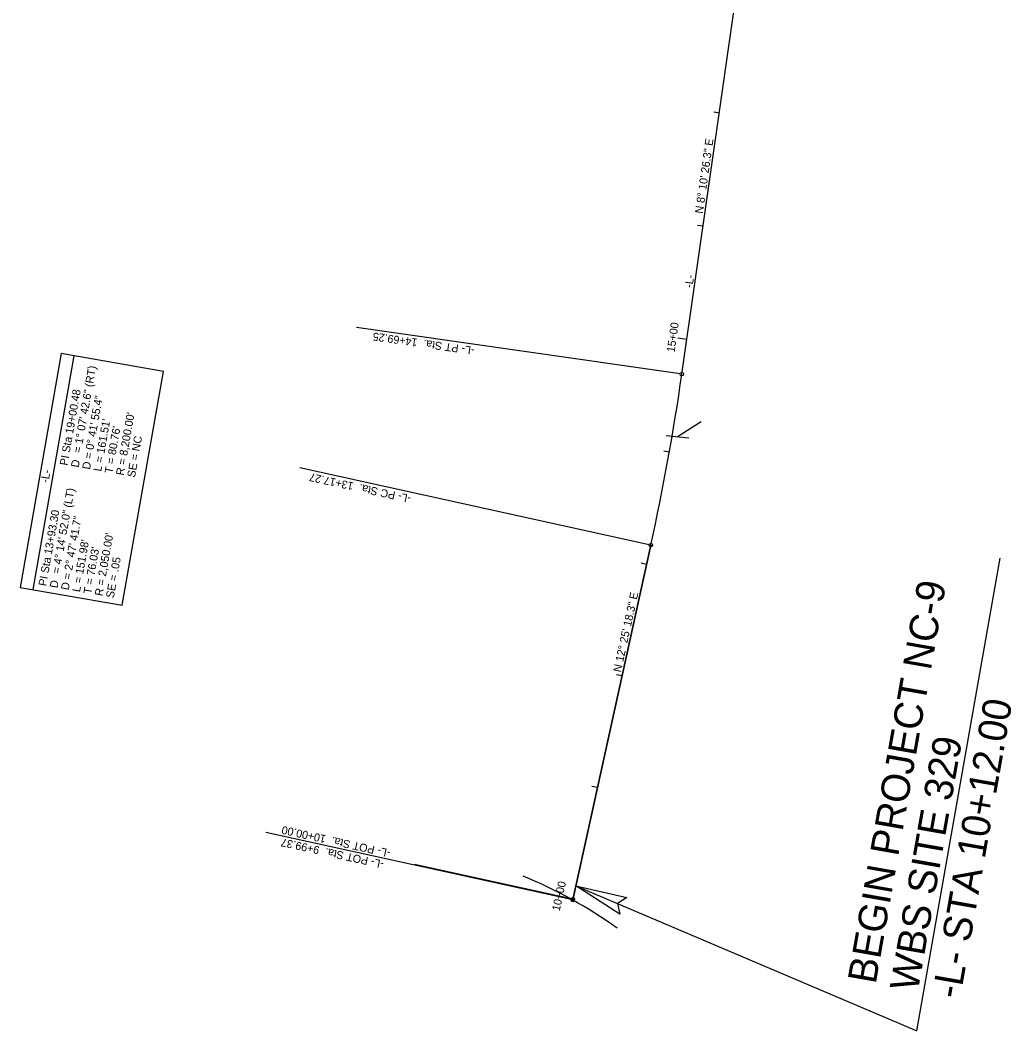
# Model space of a CAD drawing. Extents: x 1019959 to 1023888, y 635993 to 644996.
# Drawn here: x 1019959 to 1020827, y 635993 to 636877 of the extents above; entities that cross this region are included whole.
import ezdxf

# ---------------------------------------------------------------- set-up
doc = ezdxf.new("R2010")
doc.units = 0
for name, color, linetype in [('Cogo Default Point CELL', 7, 'Continuous'), ('COGO Default Point Elevation', 7, 'Continuous'), ('COGO Default Point Number', 7, 'Continuous'), ('Exist Other Culture Well CELL', 7, 'Continuous'), ('Exist Roads EOT', 7, 'Continuous'), ('Exist Structure Minor Pipes CMP 18 Inch Cogo Comment', 7, 'Continuous'), ('Exist Structure Minor Pipes CMP 18 Inch Cogo Point CELL', 7, 'Continuous'), ('Exist Structure Minor Pipes CMP 24 Inch Cogo Number', 7, 'Continuous'), ('Exist Structure Minor Pipes CMP 24 Inch Cogo Point CELL', 7, 'Continuous'), ('Exist Utilities Power Pole CELL', 7, 'Continuous'), ('Exist Utilities Power Pole Cogo Elevation', 7, 'Continuous'), ('Exist Utilities Power Pole Cogo Number', 7, 'Continuous')]:
    doc.layers.add(name, color=color, linetype=linetype)

msp = doc.modelspace()

# ---------------------------------------------------------------- linework, layer by layer
at = {"layer": 'COGO Default Point Elevation'}
for p, q in [((1020570.96, 636795.63), (1020566.01, 636796.34)), ((1020556.74, 636696.65), (1020551.79, 636697.36)), ((1020527.15, 636498.86), (1020522.22, 636499.73)), ((1020507.27, 636400.86), (1020502.39, 636401.94)), ((1020485.76, 636303.2), (1020480.88, 636304.28)), ((1020464.25, 636205.54), (1020459.37, 636206.62))]:
    msp.add_line(p, q, dxfattribs=at)
at = {"layer": 'COGO Default Point Number'}
for p, q in [((1020542.52, 636597.66), (1020534.6, 636598.8)), ((1020442.74, 636107.88), (1020434.93, 636109.6))]:
    msp.add_line(p, q, dxfattribs=at)
at = {"layer": 'Exist Other Culture Well CELL'}
for p, q in [((1020743.9, 635992.82), (1020816.69, 636406.23)), ((1020445.32, 636119.6), (1020743.9, 635992.82))]:
    msp.add_line(p, q, dxfattribs=at)
at = {"layer": 'Exist Roads EOT'}
for p, q in [((1020536.66, 636567.44), (1020253.2, 636608.16)), ((1020509.52, 636418.05), (1020203.76, 636485.4)), ((1020441.14, 636107.59), (1020174.04, 636166.42)), ((1020441.27, 636108.21), (1020304.16, 636138.41))]:
    msp.add_line(p, q, dxfattribs=at)
for centre in [(1020538.15, 636567.23), (1020510.99, 636417.73), (1020442.6, 636107.27), (1020442.74, 636107.88)]:
    msp.add_circle(centre, 1.5, dxfattribs=at)
at = {"layer": 'Exist Structure Minor Pipes CMP 18 Inch Cogo Comment'}
msp.add_lwpolyline([(1020483.71, 636094.88), (1020445.32, 636119.6), (1020490.1, 636109.28), (1020481.68, 636104.16)], close=True, dxfattribs=at)
at = {"layer": 'Exist Structure Minor Pipes CMP 18 Inch Cogo Point CELL'}
msp.add_arc((1020243.35, 635749.65), 409.38, 54.42838, 67.60673, dxfattribs=at)
at = {"layer": 'Exist Structure Minor Pipes CMP 24 Inch Cogo Number'}
for p, q in [((1020534.34, 636512.56), (1020555.09, 636525.94)), ((1020524.36, 636513.55), (1020544.32, 636511.58))]:
    msp.add_line(p, q, dxfattribs=at)
at = {"layer": 'Exist Structure Minor Pipes CMP 24 Inch Cogo Point CELL'}
for p, q in [((1020538.15, 636567.23), (1020587.98, 636914.14)), ((1020510.99, 636417.73), (1020442.6, 636107.27))]:
    msp.add_line(p, q, dxfattribs=at)
msp.add_arc((1018508.98, 636858.7), 2050, 347.57825, 351.82602, dxfattribs=at)
at = {"layer": 'Exist Utilities Power Pole CELL'}
for p, q in [((1020538.15, 636567.23), (1020587.98, 636914.14)), ((1020442.6, 636107.27), (1020510.99, 636417.73))]:
    msp.add_line(p, q, dxfattribs=at)
msp.add_arc((1018508.98, 636858.7), 2050, 347.57825, 351.82602, dxfattribs=at)
at = {"layer": 'Exist Utilities Power Pole Cogo Elevation'}
msp.add_line((1019970.14, 636378.76), (1020006.15, 636583.22), dxfattribs=at)
msp.add_lwpolyline([(1020048.3, 636365), (1020084.31, 636569.46), (1019994.93, 636585.2), (1019958.93, 636380.74)], close=True, dxfattribs=at)

# ---------------------------------------------------------------- texts
at = {"layer": 'Cogo Default Point CELL'}
for s, rotation, p in [('15+00', 81.82602, (1020531.75, 636585.96)), ('10+00', 77.57825, (1020431.15, 636097.12))]:
    msp.add_text(s, height=7, rotation=rotation, dxfattribs=at).set_placement(p)
at = {"layer": 'Exist Other Culture Well CELL'}
for s, p in [('BEGIN PROJECT NC-9', (1020707.77, 636033.04)), ('-L- STA 10+12.00', (1020781.63, 636020.03)), ('WBS SITE 329', (1020744.7, 636026.54))]:
    msp.add_text(s, height=25, rotation=80.01425, dxfattribs=at).set_placement(p)
at = {"layer": 'Exist Roads EOT'}
for s, rotation, p in [('-L- PT Sta.  14+69.25', 171.82602, (1020357, 636590.98)), ('-L- PC Sta.  13+17.27', 167.57825, (1020301.56, 636461.25)), ('-L- POT Sta.  10+00.00', 167.57825, (1020283.48, 636151.26)), ('-L- POT Sta.  9+99.37', 167.57825, (1020277.8, 636141.52))]:
    msp.add_text(s, height=7, rotation=rotation, dxfattribs=at).set_placement(p)
at = {"layer": 'Exist Utilities Power Pole Cogo Elevation'}
for s, p in [('= 1%%d 07\' 42.6" (RT)', (1020012.07, 636497.89)), ('PI Sta 19+00.48', (1020000.29, 636486.92)), ('D = 0%%d 41\' 55.4"', (1020019.98, 636483.45)), ("L = 161.51'", (1020029.83, 636481.72)), ("R = 8,200.00'", (1020049.53, 636478.25)), ("T = 80.76'", (1020039.68, 636479.98)), ('SE = NC', (1020059.38, 636476.51)), ('D', (1020010.13, 636485.18)), ('-L-', (1019983.63, 636471.82)), ('= 4%%d 14\' 52.0" (LT)', (1019993.49, 636392.39)), ('PI Sta 13+93.30', (1019981.71, 636381.42)), ('D = 2%%d 47\' 41.7"', (1020001.41, 636377.95)), ("L = 151.98'", (1020011.25, 636376.22)), ("R = 2,050.00'", (1020030.95, 636372.75)), ("T = 76.03'", (1020021.1, 636374.48)), ('SE = .05', (1020040.8, 636371.01)), ('D', (1019991.56, 636379.68))]:
    msp.add_text(s, height=7, rotation=80.01311, dxfattribs=at).set_placement(p)
at = {"layer": 'Exist Utilities Power Pole Cogo Number'}
for s, rotation, p in [('N 8%%d 10\' 26.3" E', 81.82602, (1020556.46, 636707.35)), ('-L-', 81.82602, (1020547.37, 636642.42)), ('N 12%%d 25\' 18.3" E', 77.57825, (1020484.72, 636306.06))]:
    msp.add_text(s, height=7, rotation=rotation, dxfattribs=at).set_placement(p)

doc.saveas('drawing.dxf')
